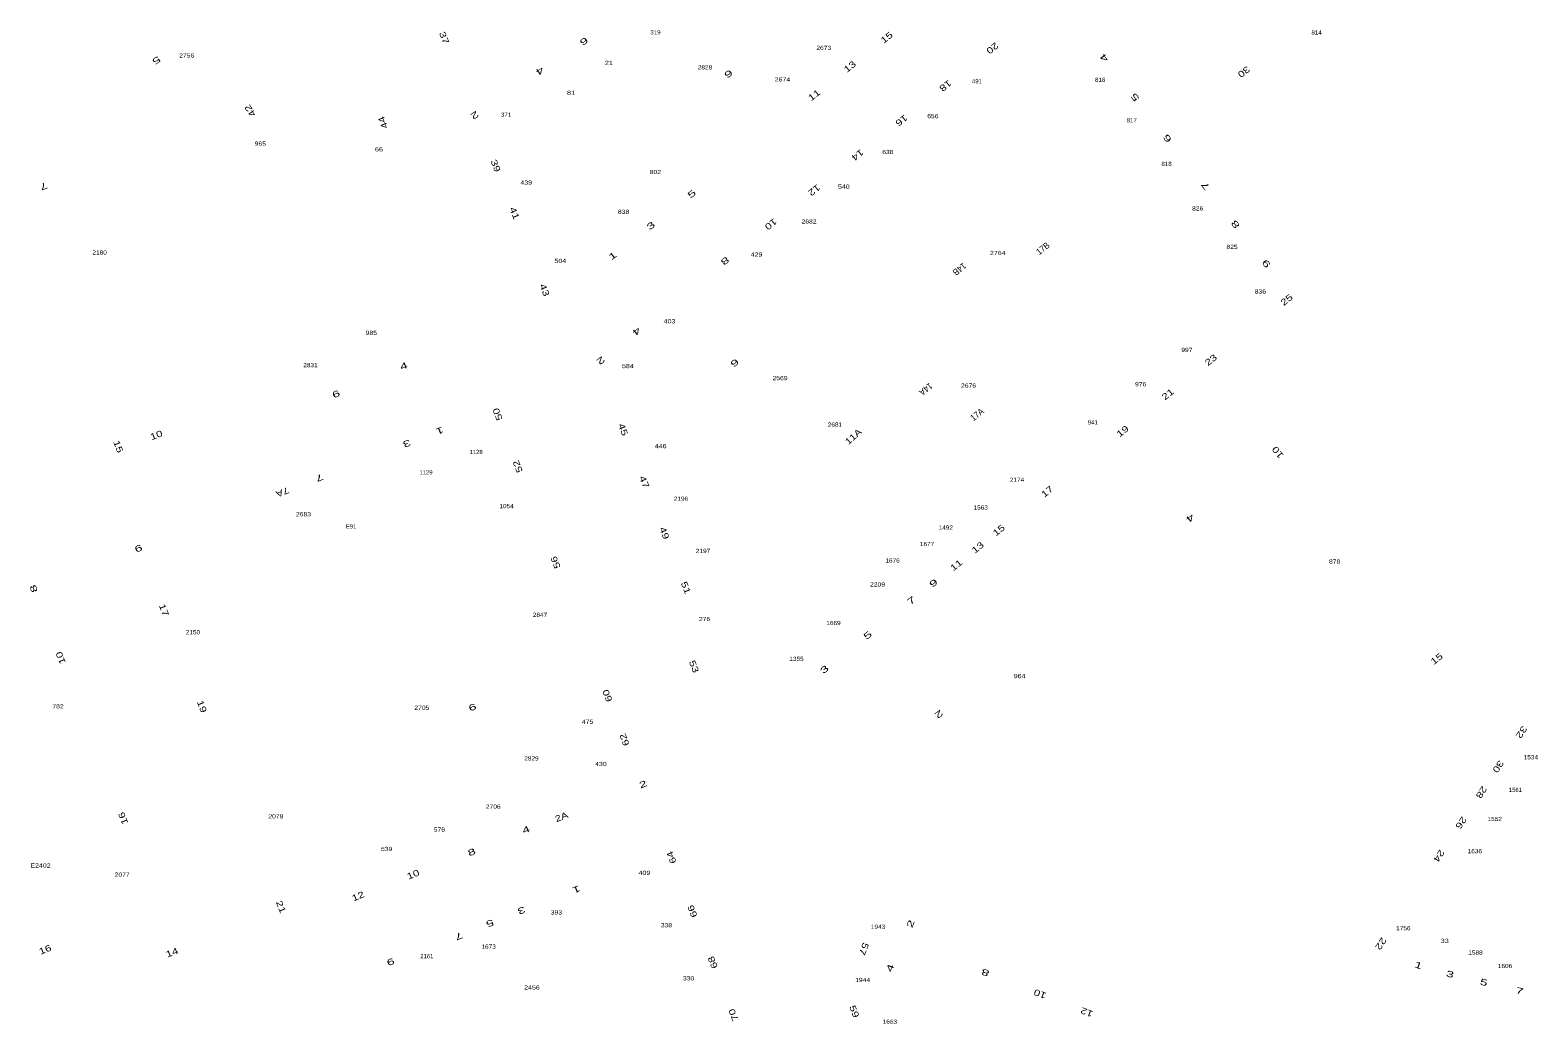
# Model space of a CAD drawing. Extents: x -828673 to -815583, y -1077737 to -1063807.
# Drawn here: x -821832.5 to -821473.2, y -1071339.6 to -1071102.6 of the extents above; entities that cross this region are included whole.
import ezdxf
from ezdxf.enums import TextEntityAlignment as Align

# ---------------------------------------------------------------- set-up
doc = ezdxf.new("R2010")
doc.units = 0
doc.header["$LTSCALE"] = 0.4
doc.layers.add('1', color=7, linetype='Continuous')
doc.layers.add('2', color=7, linetype='Continuous')

msp = doc.modelspace()

# ---------------------------------------------------------------- texts
at = {"layer": '1'}
for s, width, p in [('319', 1.1, (-821683.492, -1071103.658)), ('814', 1.1, (-821525.922, -1071103.687)), ('2756', 1.2, (-821795.197, -1071109.174)), ('2673', 1.2, (-821643.373, -1071107.358)), ('21', 1.3, (-821694.564, -1071110.951)), ('2828', 1.15, (-821671.69, -1071112.02)), ('2674', 1.25, (-821653.223, -1071114.887)), ('491', 1.1, (-821606.867, -1071115.322)), ('816', 1.1, (-821577.505, -1071114.974)), ('81', 1.3, (-821703.609, -1071118.064)), ('371', 1.1, (-821719.091, -1071123.306)), ('656', 1.2, (-821617.377, -1071123.645)), ('817', 1.1, (-821569.991, -1071124.639)), ('965', 1.2, (-821777.653, -1071130.189)), ('66', 1.3, (-821749.376, -1071131.56)), ('638', 1.2, (-821628.112, -1071132.192)), ('818', 1.1, (-821561.685, -1071135.038)), ('802', 1.2, (-821683.498, -1071136.969)), ('439', 1.25, (-821714.292, -1071139.475)), ('540', 1.25, (-821638.604, -1071140.443)), ('826', 1.2, (-821554.26, -1071145.644)), ('838', 1.2, (-821691.086, -1071146.452)), ('2682', 1.2, (-821646.878, -1071148.766)), ('2180', 1.15, (-821815.95, -1071156.15)), ('429', 1.25, (-821659.402, -1071156.641)), ('2764', 1.25, (-821601.897, -1071156.264)), ('825', 1.2, (-821546.073, -1071154.801)), ('504', 1.25, (-821706.175, -1071158.159)), ('836', 1.2, (-821539.325, -1071165.435)), ('403', 1.25, (-821680.138, -1071172.544)), ('985', 1.2, (-821751.206, -1071175.305)), ('997', 1.2, (-821556.847, -1071179.38)), ('2831', 1.15, (-821765.71, -1071183.01)), ('584', 1.25, (-821690.062, -1071183.229)), ('2569', 1.2, (-821653.795, -1071186.103)), ('2676', 1.2, (-821608.874, -1071187.873)), ('976', 1.2, (-821567.849, -1071187.569)), ('2681', 1.15, (-821640.718, -1071197.181)), ('941', 1.1, (-821579.254, -1071196.652)), ('446', 1.25, (-821682.24, -1071202.313)), ('1128', 1.05, (-821726.23, -1071203.704)), ('1129', 1.05, (-821738.179, -1071208.564)), ('2174', 1.15, (-821597.305, -1071210.322)), ('1054', 1.15, (-821718.971, -1071216.609)), ('2196', 1.15, (-821677.41, -1071214.842)), ('1563', 1.15, (-821605.982, -1071216.944)), ('2683', 1.2, (-821767.366, -1071218.549)), ('E91', 1.05, (-821756.031, -1071221.454)), ('1492', 1.15, (-821614.301, -1071221.732)), ('2197', 1.15, (-821672.139, -1071227.291)), ('1677', 1.15, (-821618.767, -1071225.659)), ('1676', 1.15, (-821626.98, -1071229.577)), ('878', 1.2, (-821521.63, -1071229.84)), ('2209', 1.2, (-821630.558, -1071235.305)), ('2847', 1.15, (-821711, -1071242.54)), ('276', 1.2, (-821671.781, -1071243.535)), ('1669', 1.15, (-821641.068, -1071244.478)), ('2150', 1.15, (-821793.703, -1071246.679)), ('1355', 1.15, (-821649.879, -1071253.025)), ('964', 1.25, (-821596.717, -1071257.148)), ('782', 1.2, (-821825.869, -1071264.342)), ('2705', 1.2, (-821739.157, -1071264.694)), ('475', 1.25, (-821699.67, -1071268.035)), ('2829', 1.15, (-821713.04, -1071276.76)), ('430', 1.25, (-821696.487, -1071278.09)), ('1534', 1.15, (-821474.866, -1071276.485)), ('1561', 1.05, (-821478.551, -1071284.259)), ('2706', 1.2, (-821722.147, -1071288.274)), ('2078', 1.2, (-821773.961, -1071290.585)), ('1552', 1.15, (-821483.474, -1071291.217)), ('576', 1.2, (-821734.986, -1071293.713)), ('539', 1.2, (-821747.55, -1071298.35)), ('1636', 1.15, (-821488.22, -1071298.886)), ('E2402', 1.25, (-821830.044, -1071302.294)), ('2077', 1.2, (-821810.58, -1071304.471)), ('409', 1.25, (-821686.111, -1071304.049)), ('393', 1.2, (-821707.091, -1071313.489)), ('338', 1.2, (-821680.873, -1071316.538)), ('1943', 1.15, (-821630.437, -1071316.887)), ('1756', 1.15, (-821505.258, -1071317.234)), ('1673', 1.15, (-821723.245, -1071321.619)), ('33', 1.3, (-821495.396, -1071320.265)), ('2161', 1.05, (-821737.98, -1071323.921)), ('1588', 1.15, (-821488.064, -1071323.041)), ('1606', 1.15, (-821481.019, -1071326.254)), ('2456', 1.25, (-821712.916, -1071331.366)), ('330', 1.2, (-821675.594, -1071329.186)), ('1944', 1.2, (-821634.09, -1071329.582)), ('1663', 1.15, (-821627.631, -1071339.54))]:
    msp.add_text(s, height=1, dxfattribs=dict(at, width=width)).set_placement(p, align=Align.CENTER)
at = {"layer": '2'}
for s, rotation, width, p in [('37', 291.749, 1.35, (-821734.5374, -1071104.7356)), ('6', 214.017, 1.7, (-821700.9399, -1071104.7095)), ('15', 38.644, 1.35, (-821627.9174, -1071104.9936)), ('5', 213.443, 1.7, (-821802.8222, -1071109.2218)), ('20', 219.113, 1.35, (-821603.6394, -1071106.3727)), ('4', 127.922, 1.7, (-821576.0095, -1071108.7789)), ('4', 213.703, 1.7, (-821711.4433, -1071111.7798)), ('9', 35.254, 1.7, (-821665.6609, -1071113.6951)), ('13', 38.706, 1.35, (-821636.704, -1071111.93)), ('30', 218.446, 1.35, (-821543.7147, -1071112.016)), ('18', 218.552, 1.35, (-821614.8256, -1071115.3178)), ('11', 38.356, 1.35, (-821645.2099, -1071118.714)), ('5', 128.252, 1.7, (-821568.6313, -1071118.1778)), ('42', 124.208, 1.35, (-821779.4522, -1071121.4461)), ('44', 111.397, 1.35, (-821747.7177, -1071124.4096)), ('2', 214.071, 1.7, (-821726.9643, -1071122.3082)), ('16', 218.04, 1.35, (-821625.2928, -1071123.5909)), ('6', 128.362, 1.7, (-821560.9074, -1071127.9965)), ('39', 292.089, 1.35, (-821722.246, -1071135.2585)), ('14', 218.517, 1.35, (-821635.7559, -1071131.8298)), ('7', 201.557, 1.65, (-821829.5454, -1071139.1943)), ('5', 38.3, 1.7, (-821674.3753, -1071142.2691)), ('12', 218.814, 1.35, (-821646.1129, -1071140.216)), ('7', 128.165, 1.7, (-821551.8268, -1071139.3135)), ('41', 291.446, 1.35, (-821717.7602, -1071146.5558)), ('3', 38.616, 1.7, (-821684.1321, -1071149.8594)), ('10', 218.694, 1.35, (-821656.4461, -1071148.3147)), ('8', 128.569, 1.7, (-821544.7176, -1071148.4871)), ('17B', 38.437, 0.95, (-821590.6982, -1071155.2769)), ('1', 38.767, 1.7, (-821693.2326, -1071157.0304)), ('8', 218.511, 1.7, (-821667.3785, -1071157.0728)), ('14B', 218.667, 0.95, (-821611.4954, -1071159.0454)), ('9', 128.704, 1.7, (-821537.3428, -1071157.858)), ('43', 291.494, 1.35, (-821710.6029, -1071164.8477)), ('25', 38.407, 1.35, (-821532.5954, -1071167.5226)), ('4', 218.579, 1.7, (-821688.4288, -1071173.8717)), ('2', 218.72, 1.7, (-821696.9649, -1071180.843)), ('23', 38.712, 1.35, (-821550.6531, -1071181.8688)), ('4', 21.207, 1.65, (-821743.2158, -1071183.4112)), ('6', 218.241, 1.7, (-821665.0833, -1071181.3862)), ('14A', 217.719, 0.95, (-821619.5182, -1071187.6483)), ('6', 21.379, 1.65, (-821759.3324, -1071190.0944)), ('21', 38.686, 1.35, (-821560.9218, -1071190.0335)), ('50', 111.367, 1.35, (-821720.413, -1071193.9443)), ('17A', 38.668, 0.95, (-821606.3836, -1071194.8586)), ('10', 20.998, 1.35, (-821802.1692, -1071199.8983)), ('1', 201.574, 1.65, (-821735.1457, -1071197.4257)), ('45', 290.961, 1.35, (-821691.8854, -1071198.1237)), ('11A', 41.596, 1.25, (-821635.8444, -1071200.1101)), ('19', 38.704, 1.35, (-821571.7, -1071198.8481)), ('15', 291.466, 1.35, (-821812.1897, -1071202.1955)), ('3', 201.383, 1.65, (-821743.0065, -1071200.5157)), ('10', 128.29, 1.35, (-821534.5947, -1071202.8647)), ('52', 111.563, 1.35, (-821715.6118, -1071206.4031)), ('7', 201.433, 1.65, (-821763.8169, -1071208.6563)), ('47', 292.366, 1.35, (-821686.8289, -1071210.6296)), ('7A', 201.323, 1.3, (-821772.6483, -1071212.1013)), ('17', 38.666, 1.35, (-821589.6601, -1071213.2327)), ('4', 218.182, 1.7, (-821556.5124, -1071218.411)), ('49', 291.298, 1.35, (-821682.0488, -1071222.8011)), ('15', 38.549, 1.35, (-821601.1984, -1071222.4523)), ('9', 201.498, 1.65, (-821806.9617, -1071225.5013)), ('13', 39.527, 1.35, (-821606.2133, -1071226.5605)), ('56', 111.653, 1.35, (-821706.6151, -1071229.2647)), ('11', 38.539, 1.35, (-821611.3543, -1071230.7656)), ('51', 291.208, 1.35, (-821676.921, -1071235.8422)), ('9', 38.859, 1.7, (-821616.7661, -1071235.0497)), ('8', 111.213, 1.65, (-821830.9689, -1071235.5359)), ('7', 38.68, 1.7, (-821622.0442, -1071239.2119)), ('17', 291.539, 1.35, (-821801.3226, -1071241.1517)), ('5', 37.883, 1.7, (-821632.462, -1071247.4974)), ('10', 111.221, 1.35, (-821824.5373, -1071252.029)), ('15', 38.058, 1.35, (-821496.8358, -1071253.102)), ('53', 291.378, 1.35, (-821674.9898, -1071254.6226)), ('3', 39.468, 1.7, (-821642.7562, -1071255.6295)), ('60', 111.583, 1.35, (-821694.2513, -1071261.0524)), ('19', 291.539, 1.35, (-821792.2776, -1071264.1607)), ('6', 21.075, 1.65, (-821726.8427, -1071264.7805)), ('2', 218.446, 1.7, (-821616.3937, -1071265.1573)), ('62', 110.997, 1.35, (-821690.1727, -1071271.5532)), ('32', 236.52, 1.35, (-821477.7111, -1071269.5993)), ('30', 236.327, 1.35, (-821483.2599, -1071277.8162)), ('2', 21.441, 1.65, (-821686.1882, -1071283.1226)), ('28', 236.609, 1.35, (-821487.2612, -1071283.9317)), ('16', 111.213, 1.35, (-821809.6522, -1071290.2839)), ('2A', 21.762, 1.3, (-821705.6101, -1071290.9016)), ('26', 236.545, 1.35, (-821492.1098, -1071291.214)), ('4', 21.665, 1.65, (-821714.0739, -1071293.954)), ('8', 21.145, 1.65, (-821727.0315, -1071299.3072)), ('64', 111.822, 1.35, (-821678.9775, -1071299.6078)), ('24', 236.502, 1.35, (-821497.3676, -1071299.1021)), ('10', 21.801, 1.35, (-821740.966, -1071304.6312)), ('1', 201.434, 1.65, (-821702.5739, -1071306.8013)), ('12', 23.189, 1.35, (-821754.0808, -1071309.8225)), ('21', 291.376, 1.35, (-821773.4208, -1071311.9306)), ('3', 201.494, 1.65, (-821715.6817, -1071311.8413)), ('66', 111.192, 1.35, (-821673.9797, -1071312.4376)), ('5', 201.958, 1.65, (-821723.2185, -1071314.8816)), ('2', 69.444, 1.65, (-821621.9926, -1071315.9553)), ('16', 22.042, 1.35, (-821828.662, -1071322.5432)), ('7', 201.881, 1.65, (-821730.612, -1071317.9664)), ('57', 249.001, 1.35, (-821634.5177, -1071321.4117)), ('22', 236.586, 1.35, (-821511.2288, -1071320.0425)), ('14', 21.222, 1.35, (-821798.434, -1071323.2346)), ('9', 200.749, 1.65, (-821746.8658, -1071324.0794)), ('68', 111.657, 1.35, (-821669.1452, -1071324.6458)), ('4', 69.429, 1.65, (-821626.8624, -1071326.4955)), ('8', 158.934, 1.65, (-821604.6029, -1071326.6524)), ('1', 341.085, 1.65, (-821501.8986, -1071326.2984)), ('3', 344.195, 1.65, (-821494.3238, -1071328.4188)), ('10', 159.321, 1.35, (-821591.5762, -1071331.7304)), ('5', 346.064, 1.65, (-821486.2541, -1071330.3768)), ('7', 346.913, 1.65, (-821477.7123, -1071332.4154)), ('59', 291.334, 1.35, (-821636.7958, -1071336.8711)), ('70', 112.439, 1.35, (-821664.1988, -1071337.1523)), ('12', 159.529, 1.35, (-821580.4317, -1071336.0886))]:
    msp.add_text(s, height=1.5, rotation=rotation, dxfattribs=dict(at, width=width)).set_placement(p, align=Align.CENTER)

doc.saveas('drawing.dxf')
